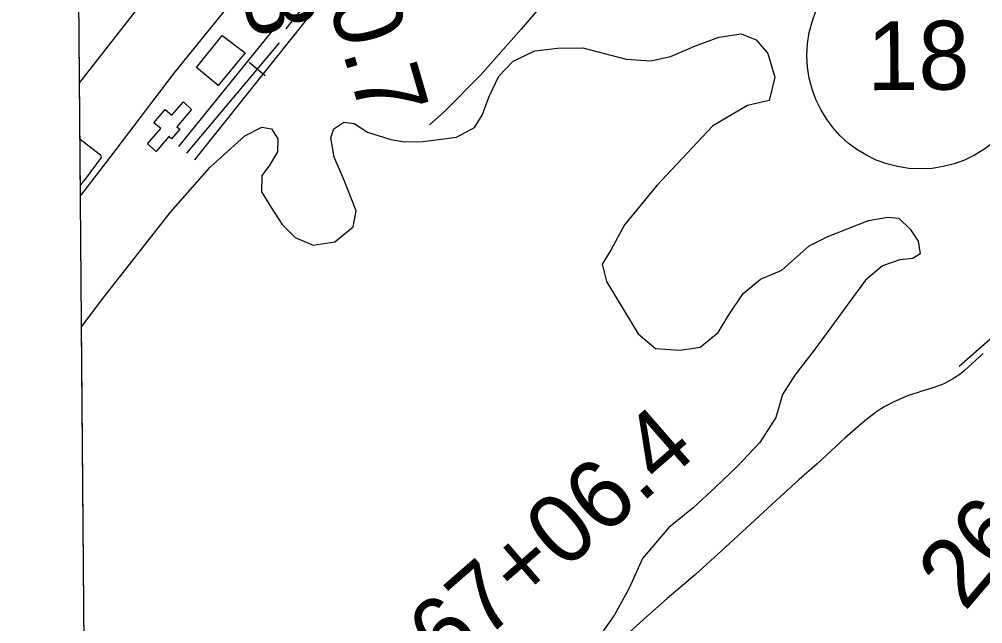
# Model space of a CAD drawing. Extents: x 3568792 to 3606828, y 529143 to 554785.
# Drawn here: x 3570936 to 3572337, y 540958 to 541836 of the extents above; entities that cross this region are included whole.
import ezdxf

# ---------------------------------------------------------------- set-up
doc = ezdxf.new("R2010")
doc.units = 0
for name, color, linetype in [('V-BLDG-OTLN', 7, 'Continuous'), ('V-GRID-FRAM', 7, 'Continuous'), ('V-ROAD-CNTR', 7, 'Continuous'), ('V-ROAD-IDEN', 7, 'Continuous'), ('V-SITE-VEGE', 7, 'Continuous'), ('V-SURV-IDEN', 7, 'Continuous'), ('V-TOPO-SHOR', 7, 'Continuous')]:
    doc.layers.add(name, color=color, linetype=linetype)

msp = doc.modelspace()

# ---------------------------------------------------------------- linework, layer by layer
at = {"layer": 'V-BLDG-OTLN'}
for points in [[(3571231.1, 541812.8), (3571264.7, 541787.7), (3571225.5, 541740), (3571193.9, 541766.2)], [(3571186.6, 541705.3), (3571165.2, 541680.1), (3571169.4, 541676.6), (3571157.4, 541662.5), (3571153.6, 541665.7), (3571135.3, 541644.3), (3571122.7, 541655.1), (3571141.7, 541677.3), (3571131.9, 541685.7), (3571148.4, 541705), (3571158, 541696.8), (3571174.7, 541716.3)]]:
    msp.add_lwpolyline(points, close=True, dxfattribs=at)
at = {"layer": 'V-GRID-FRAM'}
msp.add_lwpolyline([(3570936, 552713.8), (3602582.8, 552980.8), (3602744.1, 534798.4), (3571081.5, 534531.3), (3570936, 552713.8)], dxfattribs=at)
at = {"layer": 'V-ROAD-CNTR'}
msp.add_line((3571293.4, 541753.9), (3571270.4, 541773.3), dxfattribs=at)
for points in [[(3571673.6, 542290.9), (3571311.8, 541831.5)], [(3571687.6, 542284.5), (3571323.6, 541822.2)], [(3571701.6, 542278), (3571335.4, 541812.9)], [(3571965.5, 542151.8), (3571945.4, 542129.8), (3571904.7, 542084), (3571843.5, 542016.9), (3571780, 541950.7), (3571723.7, 541889.8), (3571666.1, 541821.9), (3571607.1, 541755.3), (3571553.8, 541701.9), (3571532.5, 541682.9)], [(3571310.2, 541827), (3571167.7, 541651.5)], [(3571336.5, 541814.1), (3571190.6, 541632.2)], [(3571314.2, 541801.8), (3571179.1, 541641.8)], [(3572423.7, 541437.8), (3572302.8, 541331.8)], [(3572337.8, 541350.6), (3572310.5, 541325.7), (3572306.7, 541322.5), (3572302.8, 541319.5), (3572298.8, 541316.7), (3572294.7, 541314), (3572290.4, 541311.5), (3572286, 541309.1), (3572281.6, 541307), (3572277.1, 541305), (3572263, 541300.1), (3572248.8, 541295.6), (3572241.8, 541293.5), (3572234.9, 541291.3), (3572228, 541288.8), (3572221.2, 541286.2), (3572214.5, 541283.3), (3572207.9, 541280.2), (3572201.4, 541276.9), (3572195, 541273.4), (3572188.7, 541269.7), (3572182.6, 541265.8)], [(3572182.6, 541265.8), (3572165.7, 541252.5), (3572137, 541227.8), (3572096.2, 541190.2), (3572069.8, 541166.7), (3572037.3, 541137.5), (3571999.1, 541102), (3571958, 541064.4), (3571919.6, 541029.4), (3571878.4, 540994.2), (3571844.4, 540964.4), (3571804.5, 540928)]]:
    msp.add_lwpolyline(points, dxfattribs=at)
at = {"layer": 'V-ROAD-IDEN'}
msp.add_circle((3572246.6, 541783.7), 165, dxfattribs=at)
at = {"layer": 'V-SITE-VEGE'}
for p, q in [((3571025.1, 541580.3), (3571021.9, 541971.8)), ((3571299.4, 541929), (3571160.8, 541758)), ((3571917.2, 541796.9), (3571953.3, 541810.3)), ((3571953.3, 541810.3), (3571986.1, 541815.2)), ((3571986.1, 541815.2), (3572007.9, 541806.2)), ((3571685.8, 541790.2), (3571718.7, 541794.4)), ((3571718.7, 541794.4), (3571755.5, 541794.8)), ((3571755.5, 541794.8), (3571818.8, 541778.2)), ((3571883.2, 541782.1), (3571917.2, 541796.9)), ((3572007.9, 541806.2), (3572024.5, 541786.6)), ((3571654.4, 541775.5), (3571685.8, 541790.2)), ((3571854.3, 541775.9), (3571883.2, 541782.1)), ((3572024.5, 541786.6), (3572034.7, 541751.9)), ((3571633.5, 541753.6), (3571654.4, 541775.5)), ((3571818.8, 541778.2), (3571854.3, 541775.9)), ((3571160.8, 541758), (3571067.4, 541634.7)), ((3571619.3, 541723.9), (3571633.5, 541753.6)), ((3572034.7, 541751.9), (3572026.4, 541718.3)), ((3571609.1, 541696.8), (3571619.3, 541723.9)), ((3571994.9, 541710.7), (3571944.5, 541681.4)), ((3572026.4, 541718.3), (3571994.9, 541710.7)), ((3571598, 541679), (3571609.1, 541696.8)), ((3571393.6, 541677.2), (3571407.9, 541686.5)), ((3571407.9, 541686.5), (3571423.1, 541684.7)), ((3571423.1, 541684.7), (3571442.3, 541672.3)), ((3571264.1, 541666.8), (3571289, 541679.5)), ((3571289, 541679.5), (3571302.8, 541677)), ((3571302.8, 541677), (3571312.1, 541662.6)), ((3571389.1, 541664), (3571393.6, 541677.2)), ((3571442.3, 541672.3), (3571476.5, 541661.5)), ((3571571.9, 541664.9), (3571598, 541679)), ((3571944.5, 541681.4), (3571863.1, 541594.5)), ((3571213.2, 541621), (3571264.1, 541666.8)), ((3571312.1, 541662.6), (3571311.7, 541643.6)), ((3571393.9, 541635.7), (3571389.1, 541664)), ((3571476.5, 541661.5), (3571496.3, 541658.3)), ((3571496.3, 541658.3), (3571523.3, 541658.6)), ((3571523.3, 541658.6), (3571571.9, 541664.9)), ((3571311.7, 541643.6), (3571299.3, 541623.1)), ((3571067.4, 541634.7), (3571025.1, 541580.3)), ((3571408, 541603.6), (3571393.9, 541635.7)), ((3571155.9, 541556.1), (3571213.2, 541621)), ((3571299.3, 541623.1), (3571288.9, 541609.2)), ((3571288.9, 541609.2), (3571288.5, 541585.5)), ((3571426.2, 541557.8), (3571408, 541603.6)), ((3571288.5, 541585.5), (3571302.5, 541562.6)), ((3571863.1, 541594.5), (3571816.3, 541537.5)), ((3571057.7, 541430.2), (3571155.9, 541556.1)), ((3571302.5, 541562.6), (3571318.5, 541537.8)), ((3571421.8, 541534.7), (3571426.2, 541557.8)), ((3572111.7, 541520.4), (3572171.3, 541544)), ((3572171.3, 541544), (3572198.9, 541548.8)), ((3572198.9, 541548.8), (3572215.3, 541547)), ((3572215.3, 541547), (3572231.9, 541531.3)), ((3571318.5, 541537.8), (3571337.1, 541518.9)), ((3571395, 541512.8), (3571421.8, 541534.7)), ((3571816.3, 541537.5), (3571796.2, 541500.5)), ((3572231.9, 541531.3), (3572243.2, 541513.7)), ((3571337.1, 541518.9), (3571363.5, 541507.9)), ((3572084.8, 541507), (3572111.7, 541520.4)), ((3571363.5, 541507.9), (3571395, 541512.8)), ((3571796.2, 541500.5), (3571783.9, 541480.1)), ((3572045, 541471.8), (3572084.8, 541507)), ((3572243.2, 541513.7), (3572246, 541495.3)), ((3572216.5, 541486.5), (3572191.6, 541477.7)), ((3572235.6, 541488.6), (3572216.5, 541486.5)), ((3572246, 541495.3), (3572235.6, 541488.6)), ((3571783.9, 541480.1), (3571790, 541455.1)), ((3572014.2, 541458.4), (3572045, 541471.8)), ((3572191.6, 541477.7), (3572166.8, 541457.1)), ((3571988.8, 541437.8), (3572014.2, 541458.4)), ((3571790, 541455.1), (3571805.4, 541429.6)), ((3572166.8, 541457.1), (3572144.1, 541426)), ((3571026.6, 541389.2), (3571057.7, 541430.2)), ((3571968, 541406.7), (3571988.8, 541437.8)), ((3571805.4, 541429.6), (3571836.1, 541379.3)), ((3572144.1, 541426), (3572116.1, 541388.3)), ((3571952.5, 541380.9), (3571968, 541406.7)), ((3571037.6, 540015.4), (3571026.6, 541389.2)), ((3572116.1, 541388.3), (3572092.1, 541355.2)), ((3571836.1, 541379.3), (3571861.3, 541357.8)), ((3571926.3, 541359.7), (3571952.5, 541380.9)), ((3571861.3, 541357.8), (3571897.4, 541355.5)), ((3571897.4, 541355.5), (3571926.3, 541359.7)), ((3572092.1, 541355.2), (3572064.1, 541318.8)), ((3572064.1, 541318.8), (3572046, 541291)), ((3572046, 541291), (3572036.4, 541257.4)), ((3572036.4, 541257.4), (3572013, 541221)), ((3572013, 541221), (3571979.8, 541185.9)), ((3571979.8, 541185.9), (3571948.5, 541156)), ((3571948.5, 541156), (3571915.9, 541126.1)), ((3571915.9, 541126.1), (3571880.7, 541097.6)), ((3571880.7, 541097.6), (3571842.3, 541052.5)), ((3571842.3, 541052.5), (3571822.9, 541009.6)), ((3571822.9, 541009.6), (3571801.6, 540970.6)), ((3571801.6, 540970.6), (3571771.7, 540927.6))]:
    msp.add_line(p, q, dxfattribs=at)
at = {"layer": 'V-TOPO-SHOR'}
for points in [[(3571486.3, 542344.6), (3571444.3, 542290.8), (3571382, 542211.5), (3571304.1, 542109.3), (3571227.5, 542009.8), (3571149.2, 541905.3), (3571023.7, 541744.4)], [(3571024.4, 541662.1), (3571053.9, 541639.3), (3571055.3, 541635.4), (3571033.2, 541605.9), (3571024.9, 541595.7)]]:
    msp.add_lwpolyline(points, dxfattribs=at)

# ---------------------------------------------------------------- texts
at = {"layer": 'V-ROAD-IDEN'}
msp.add_text('18', height=100, rotation=0.4833, dxfattribs=at).set_placement((3572169.5, 541733.1))
at = {"layer": 'V-SURV-IDEN'}
for s, rotation, p in [('2649+48.8', 286.0907, (3571101.8, 542415)), ('2650+30.7', 286.2545, (3571259.1, 542292.5)), ('2667+81.6', 49.5551, (3572311, 540974)), ('2667+06.4', 41.0511, (3571444.8, 540787.2))]:
    msp.add_text(s, height=100, rotation=rotation, dxfattribs=at).set_placement(p)

doc.saveas('drawing.dxf')
